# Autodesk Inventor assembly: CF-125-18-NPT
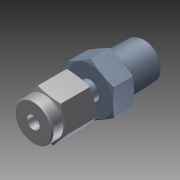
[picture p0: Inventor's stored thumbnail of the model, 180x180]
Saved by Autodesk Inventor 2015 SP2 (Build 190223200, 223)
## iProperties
Created: 2017-10
Part Number: CF-125-18-NPT
Document SubType Name: Assembly
Designer: JN
Author: JN
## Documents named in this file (5)
- C:\Users\JN\Documents\CAD Drawings\The Sensor Connection\3D\CF\CF-0250-18-NPT\3D\CF-125-18-NPT.iam
- C:\Users\JN\Documents\CAD Drawings\The Sensor Connection\3D\CF\CF-0250-18-NPT\3D\Imported Components\CF-0125-18-NPT Threaded Body\CF-0125-18-NPT Threaded Body.ipt
- C:\Users\JN\Documents\CAD Drawings\The Sensor Connection\3D\CF\CF-0250-18-NPT\3D\Imported Components\CF-0125-NPT Bottom Ferrule\CF-0125-NPT Bottom Ferrule.ipt
- C:\Users\JN\Documents\CAD Drawings\The Sensor Connection\3D\CF\CF-0250-18-NPT\3D\Imported Components\CF-0125-NPT Cap\CF-0125-NPT Cap.ipt
- C:\Users\JN\Documents\CAD Drawings\The Sensor Connection\3D\CF\CF-0250-18-NPT\3D\Imported Components\CF-0125-NPT Top Ferrule\CF-0125-NPT Top Ferrule.ipt
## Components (4 placed, 4 different names)
1. CF-0125-18-NPT Threaded Body:1 — Mate:1, Mate:2, Rotation:1
2. CF-0125-NPT Bottom Ferrule:1 — Mate:1, Mate:2, Mate:3, Mate:4
3. CF-0125-NPT Cap:1 — Mate:5, Mate:6, Rotation:1
4. CF-0125-NPT Top Ferrule:1 — Mate:3, Mate:4, Mate:5, Mate:6
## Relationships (7: Mate 6, RelateRotation 1)
- Mate:1: CF-0125-18-NPT Threaded Body:1 ↔ CF-0125-NPT Bottom Ferrule:1
- Mate:2: CF-0125-18-NPT Threaded Body:1 ↔ CF-0125-NPT Bottom Ferrule:1
- Mate:3: CF-0125-NPT Bottom Ferrule:1 ↔ CF-0125-NPT Top Ferrule:1
- Mate:4: CF-0125-NPT Bottom Ferrule:1 ↔ CF-0125-NPT Top Ferrule:1
- Mate:5: CF-0125-NPT Cap:1 ↔ CF-0125-NPT Top Ferrule:1
- Mate:6: CF-0125-NPT Cap:1 ↔ CF-0125-NPT Top Ferrule:1
- Rotation:1 [RelateRotation]: CF-0125-18-NPT Threaded Body:1 ↔ CF-0125-NPT Cap:1
